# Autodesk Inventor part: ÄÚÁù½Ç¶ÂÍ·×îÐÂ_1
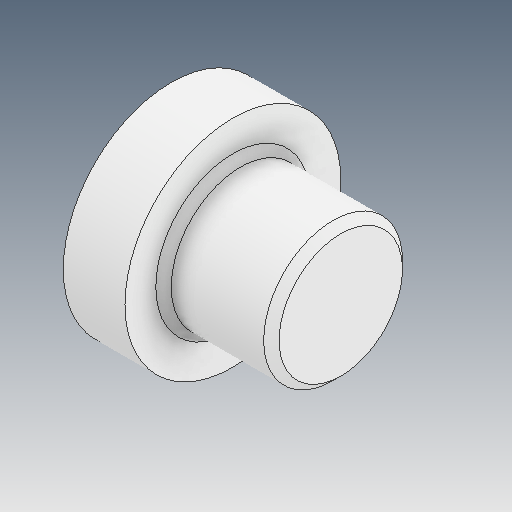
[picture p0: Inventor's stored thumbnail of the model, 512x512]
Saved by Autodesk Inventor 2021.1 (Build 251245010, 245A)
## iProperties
Created: 2021-05
Part Number: ÄÚÁù½Ç¶ÂÍ·×îÐÂ_1
Material: Ogólny
Document SubType Name: Modeling
Designer: user
Density: 1 g/cm^3
Appearance: Domyślna
Author: user
Revision Number: ÈÎºÎ
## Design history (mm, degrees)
feature "ÊäÈë1"
node "Bryła1"
